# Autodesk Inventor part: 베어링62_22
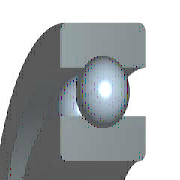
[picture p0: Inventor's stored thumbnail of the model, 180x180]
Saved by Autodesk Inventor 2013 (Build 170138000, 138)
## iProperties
Created: 2009-02
Part Number: 베어링62_22
Material: 강, 연강
Description: 깊은 그루브 볼 베어링
Document SubType Name: Modeling
Standard: KS B 2023
Designer: KYOUNG IL JANG
Standards Organization: KS
Language: ko-KR
Size Designation: 62/22 - 22 x 50 x 14
Categories: <MemberInstance><Categories><Category DisplayName="샤프트 부품" InternalName="7f7aeb1f-a693-4053-b835-cee3144e0d98" Mnemonic="SHFT"><Category DisplayName="베어링" Inter
Density: 1 g/cm^3
IsCustomPart: 0
Author: KYOUNG IL JANG
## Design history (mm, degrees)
sketch "스케치" dims "d0" = 7.28 (= -0.26 x WD + 0.26 x BD)
  geometry: L1 (3.36, 18)-(10.64, 18); L2 (7, 18)-(7, 14.36); L3 (7, 18)-(7, 21.64); L4 (4.295, 15.564)-(0, 15.564); L5 (0, 11)-(14, 11); L6 (4.295, 20.436)-(0, 20.436); L7 (0, 25)-(14, 25); L8 (14, 11)-(14, 15.564); L9 (9.705, 15.564)-(14, 15.564); L10 (9.705, 20.436)-(14, 20.436); L11 (14, 25)-(14, 20.436); L12 (-1.4, 0)-(8.4, 0) reference; L13 (0, -0.3)-(0, 5.3) reference
  constraints: 22 end point, 4 point on line, 2 collinear, 2 perpendicular, 2 symmetric about line, 1 midpoint, 1 parallel, 14 other
  dimensions: "d9" = 22 diameter of L5 L12 (= WD); "d11" = 50 diameter of L7 L12 (= BD); "d12" = 14 distance between parallel lines of L8 L13 (= KB); "d13" = 31.128 diameter of L9 L12 (= 0.326 x BD + 0.674 x WD)
revolve "본체" stored, may be unused: angle "d6" = 90 deg
revolve "볼" stored, may be unused: angle "d7" = 90 deg
pattern_circular "IDS_ARRAYBALL[SIMPL:T]" dims angle "d3" = 360 deg
body "Solid1"
fillet "모깎기1" dims "d1" = 1 (= KRS)
other parameters: "WD" = 22 [user parameter; used in 5 equation terms], "BD" = 50 [user parameter; used in 5 equation terms], "KB" = 14 [user parameter; used in 1 equation term], "KRS" = 1 [user parameter; used in 1 equation term], "d4" = 0, "d5" = 0, "d8" = 0, "d14" = 0, "d15" = 0, "BBA" = 0 [user parameter], "BC0" = 7154000 [user parameter], "BC" = 1.2233e+07 [user parameter], "BR" = 25 (= 0.5 x BD) [user parameter], "WR" = 11 (= 0.5 x WD) [user parameter]
